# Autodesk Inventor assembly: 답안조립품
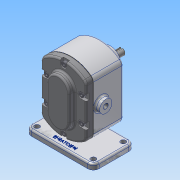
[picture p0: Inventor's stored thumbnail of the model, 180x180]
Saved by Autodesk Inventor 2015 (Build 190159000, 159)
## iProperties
Created: 2019-03
Part Number: 답안조립품
Document SubType Name: Assembly
Designer: user
Author: user
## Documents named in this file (11)
- C:\Users\user\Desktop\490307V1003\답안조립품.iam
- C:\Users\user\Desktop\490307V1003\본체.ipt
- C:\Users\user\Desktop\490307V1003\개스킷.ipt
- C:\Users\user\Desktop\490307V1003\메인축.ipt
- C:\Users\user\Desktop\490307V1003\베어링부시.ipt
- C:\Users\user\Desktop\490307V1003\볼트 M5.ipt
- C:\Users\user\Desktop\490307V1003\서브축.ipt
- C:\Users\user\Desktop\490307V1003\스퍼기어.ipt
- C:\Users\user\Desktop\490307V1003\오일 실 16 28 7.ipt
- C:\Users\user\Desktop\490307V1003\커버.ipt
- C:\Users\user\Desktop\490307V1003\키 6 x 6 x 18.ipt
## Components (1 placed, 1 different names)
1. 개스킷:1
